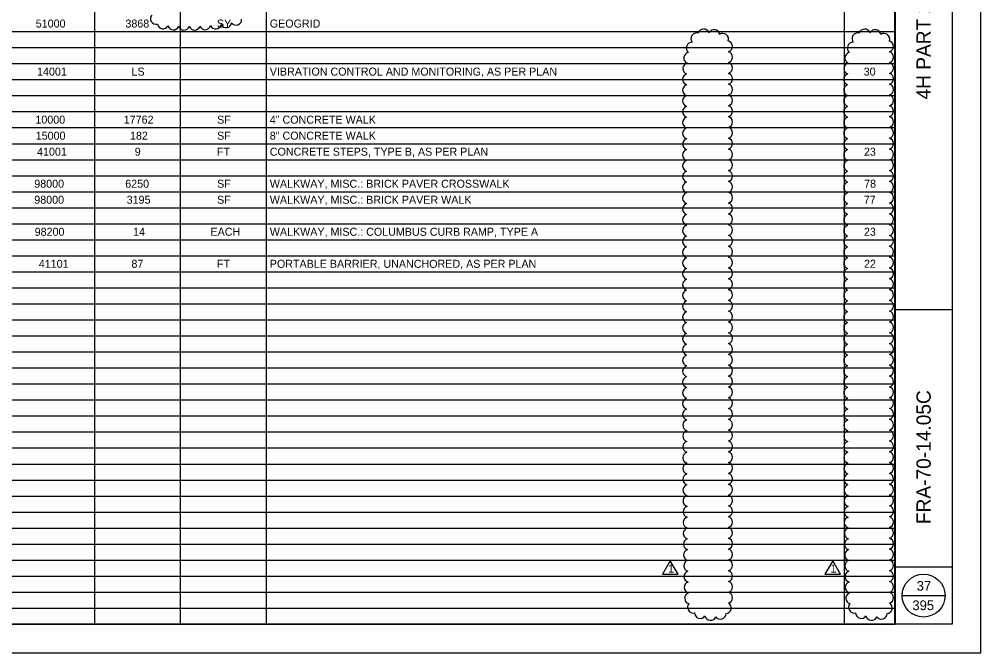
# Model space of a CAD drawing. Extents: x 0 to 34, y 0 to 22.
# Drawn here: x 17.19 to 34, y 0 to 11.08 of the extents above; entities that cross this region are included whole.
import ezdxf

# ---------------------------------------------------------------- set-up
doc = ezdxf.new("R2010")
doc.units = 0
for name, color, linetype in [('SH_Border', 7, 'Continuous'), ('SH_Cut_Line', 7, 'Continuous'), ('SH_Data', 7, 'Continuous'), ('SH_Text', 7, 'Continuous'), ('TX_P_1000', 7, 'Continuous')]:
    doc.layers.add(name, color=color, linetype=linetype)

msp = doc.modelspace()

# ---------------------------------------------------------------- linework, layer by layer
at = {"layer": 'SH_Border'}
for p, q in [((32.5, 0.5), (32.5, 21.5)), ((32.5, 6), (33.5, 6)), ((32.5, 1.5), (33.5, 1.5))]:
    msp.add_line(p, q, dxfattribs=at)
msp.add_lwpolyline([(2, 21.5), (33.5, 21.5), (33.5, 0.5), (2, 0.5)], close=True, dxfattribs=at)
at = {"layer": 'SH_Cut_Line'}
msp.add_lwpolyline([(0, 0), (34, 0), (34, 22), (0, 22)], close=True, dxfattribs=at)
at = {"layer": 'SH_Data'}
for p, q in [((18.504, 21.5), (18.504, 0.5)), ((20.002, 21.5), (20.002, 0.5)), ((21.501, 21.5), (21.501, 0.5)), ((31.614, 21.5), (31.614, 0.5)), ((32.504, 21.5), (32.504, 0.5)), ((2, 10.86), (32.504, 10.86)), ((2, 10.58), (32.504, 10.58)), ((2, 10.3), (32.504, 10.3)), ((2, 10.02), (32.504, 10.02)), ((2, 9.74), (32.504, 9.74)), ((2, 9.46), (32.504, 9.46)), ((2, 9.18), (32.504, 9.18)), ((2, 8.9), (32.504, 8.9)), ((2, 8.62), (32.504, 8.62)), ((2, 8.34), (32.504, 8.34)), ((2, 8.06), (32.504, 8.06)), ((2, 7.78), (32.504, 7.78)), ((2, 7.5), (32.504, 7.5)), ((2, 7.22), (32.504, 7.22)), ((2, 6.94), (32.504, 6.94)), ((2, 6.66), (32.504, 6.66)), ((2, 6.38), (32.504, 6.38)), ((2, 6.1), (32.504, 6.1)), ((2, 5.82), (32.504, 5.82)), ((2, 5.54), (32.504, 5.54)), ((2, 5.26), (32.504, 5.26)), ((2, 4.98), (32.504, 4.98)), ((2, 4.7), (32.504, 4.7)), ((2, 4.42), (32.504, 4.42)), ((2, 4.14), (32.504, 4.14)), ((2, 3.86), (32.504, 3.86)), ((2, 3.58), (32.504, 3.58)), ((2, 3.3), (32.504, 3.3)), ((2, 3.02), (32.504, 3.02)), ((2, 2.74), (32.504, 2.74)), ((2, 2.46), (32.504, 2.46)), ((2, 2.18), (32.504, 2.18)), ((2, 1.9), (32.504, 1.9)), ((2, 1.62), (32.504, 1.62)), ((2, 1.34), (32.504, 1.34)), ((2, 1.06), (32.504, 1.06)), ((32.625, 1), (33.375, 1)), ((2, 0.78), (32.504, 0.78)), ((2, 0.5), (32.504, 0.5))]:
    msp.add_line(p, q, dxfattribs=at)
msp.add_circle((33, 1), 0.375, dxfattribs=at)
at = {"layer": 'TX_P_1000'}
for points in [[(28.571, 1.608), (28.435, 1.372), (28.708, 1.372)], [(31.411, 1.608), (31.274, 1.372), (31.547, 1.372)]]:
    msp.add_lwpolyline(points, close=True, dxfattribs=at)
for centre, radius, start, end in [((19.578, 11.085), 0.0976, 139.2641, 284.2641), ((19.699, 11.005), 0.0976, 188.32, 333.32), ((19.88, 10.986), 0.0976, 195.1082, 340.1082), ((20.065, 10.982), 0.0976, 197.1836, 342.1836), ((20.251, 10.983), 0.0976, 198.6029, 343.6029), ((20.436, 10.99), 0.0976, 200.3873, 345.3873), ((20.62, 11.003), 0.0976, 202.8824, 347.8824), ((20.803, 11.026), 0.0976, 206.7346, 351.7346), ((20.977, 11.072), 0.0977, 217.3339, 2.3339), ((29.031, 10.736), 0.099, 74.4093, 219.4093), ((29.153, 10.805), 0.0991, 19.2496, 164.2496), ((29.336, 10.794), 0.0991, 9.041, 154.041), ((29.491, 10.729), 0.099, 340.6755, 125.6755), ((31.847, 10.736), 0.099, 74.4093, 219.4093), ((31.969, 10.805), 0.0991, 19.2496, 164.2496), ((32.152, 10.794), 0.0991, 9.041, 154.041), ((32.308, 10.729), 0.099, 340.6755, 125.6755), ((28.95, 10.574), 0.0991, 87.314, 232.314), ((29.557, 10.601), 0.0992, 288.6913, 73.6913), ((31.766, 10.574), 0.0991, 87.314, 232.314), ((32.373, 10.601), 0.0992, 288.6913, 73.6913), ((28.906, 10.398), 0.0991, 99.6335, 244.6335), ((29.559, 10.413), 0.0991, 287.5, 72.5), ((31.722, 10.398), 0.0991, 99.6335, 244.6335), ((32.375, 10.413), 0.0991, 287.5, 72.5), ((28.889, 10.213), 0.0991, 105.2456, 250.2456), ((29.559, 10.224), 0.0991, 287.5, 72.5), ((31.706, 10.213), 0.0991, 105.2456, 250.2456), ((32.375, 10.224), 0.0991, 287.5, 72.5), ((28.886, 10.025), 0.0991, 107.4797, 252.4797), ((29.559, 10.035), 0.0991, 287.5, 72.5), ((31.702, 10.025), 0.0991, 107.4797, 252.4797), ((32.375, 10.035), 0.0991, 287.5, 72.5), ((28.885, 9.836), 0.0991, 107.5, 252.5), ((29.559, 9.846), 0.0991, 287.5, 72.5), ((31.702, 9.836), 0.0991, 107.5, 252.5), ((32.375, 9.846), 0.0991, 287.5, 72.5), ((28.885, 9.647), 0.0991, 107.5, 252.5), ((29.559, 9.657), 0.0991, 287.5, 72.5), ((31.702, 9.647), 0.0991, 107.5, 252.5), ((32.375, 9.657), 0.0991, 287.5, 72.5), ((28.885, 9.458), 0.0991, 107.5, 252.5), ((29.559, 9.468), 0.0991, 287.5, 72.5), ((31.702, 9.458), 0.0991, 107.5, 252.5), ((32.375, 9.468), 0.0991, 287.5, 72.5), ((28.885, 9.269), 0.0991, 107.5, 252.5), ((29.559, 9.279), 0.0991, 287.5, 72.5), ((31.702, 9.269), 0.0991, 107.5, 252.5), ((32.375, 9.279), 0.0991, 287.5, 72.5), ((28.885, 9.08), 0.0991, 107.5, 252.5), ((29.559, 9.09), 0.0991, 287.5, 72.5), ((31.702, 9.08), 0.0991, 107.5, 252.5), ((32.375, 9.09), 0.0991, 287.5, 72.5), ((28.885, 8.891), 0.0991, 107.5, 252.5), ((29.559, 8.901), 0.0991, 287.5, 72.5), ((31.702, 8.891), 0.0991, 107.5, 252.5), ((32.375, 8.901), 0.0991, 287.5, 72.5), ((28.885, 8.702), 0.0991, 107.5, 252.5), ((29.559, 8.712), 0.0991, 287.5, 72.5), ((31.702, 8.702), 0.0991, 107.5, 252.5), ((32.375, 8.712), 0.0991, 287.5, 72.5), ((28.885, 8.513), 0.0991, 107.5, 252.5), ((29.559, 8.523), 0.0991, 287.5, 72.5), ((31.702, 8.513), 0.0991, 107.5, 252.5), ((32.375, 8.523), 0.0991, 287.5, 72.5), ((28.885, 8.324), 0.0991, 107.5, 252.5), ((29.559, 8.334), 0.0991, 287.5, 72.5), ((31.702, 8.324), 0.0991, 107.5, 252.5), ((32.375, 8.334), 0.0991, 287.5, 72.5), ((28.885, 8.135), 0.0991, 107.5, 252.5), ((29.559, 8.145), 0.0991, 287.5, 72.5), ((31.702, 8.135), 0.0991, 107.5, 252.5), ((32.375, 8.145), 0.0991, 287.5, 72.5), ((28.885, 7.946), 0.0991, 107.5, 252.5), ((29.559, 7.956), 0.0991, 287.5, 72.5), ((31.702, 7.946), 0.0991, 107.5, 252.5), ((32.375, 7.956), 0.0991, 287.5, 72.5), ((28.885, 7.757), 0.0991, 107.5, 252.5), ((29.559, 7.767), 0.0991, 287.5, 72.5), ((31.702, 7.757), 0.0991, 107.5, 252.5), ((32.375, 7.767), 0.0991, 287.5, 72.5), ((28.885, 7.568), 0.0991, 107.5, 252.5), ((29.559, 7.578), 0.0991, 287.5, 72.5), ((31.702, 7.568), 0.0991, 107.5, 252.5), ((32.375, 7.578), 0.0991, 287.5, 72.5), ((28.885, 7.379), 0.0991, 107.5, 252.5), ((29.559, 7.389), 0.0991, 287.5, 72.5), ((31.702, 7.379), 0.0991, 107.5, 252.5), ((32.375, 7.389), 0.0991, 287.5, 72.5), ((28.885, 7.19), 0.0991, 107.5, 252.5), ((29.559, 7.2), 0.0991, 287.5, 72.5), ((31.702, 7.19), 0.0991, 107.5, 252.5), ((32.375, 7.2), 0.0991, 287.5, 72.5), ((28.885, 7.001), 0.0991, 107.5, 252.5), ((29.559, 7.011), 0.0991, 287.5, 72.5), ((31.702, 7.001), 0.0991, 107.5, 252.5), ((32.375, 7.011), 0.0991, 287.5, 72.5), ((28.885, 6.812), 0.0991, 107.5, 252.5), ((29.559, 6.822), 0.0991, 287.5, 72.5), ((31.702, 6.812), 0.0991, 107.5, 252.5), ((32.375, 6.822), 0.0991, 287.5, 72.5), ((29.559, 6.633), 0.0991, 287.5, 72.5), ((32.375, 6.633), 0.0991, 287.5, 72.5), ((28.885, 6.623), 0.0991, 107.5, 252.5), ((31.702, 6.623), 0.0991, 107.5, 252.5), ((28.885, 6.434), 0.0991, 107.5, 252.5), ((29.559, 6.444), 0.0991, 287.5, 72.5), ((31.702, 6.434), 0.0991, 107.5, 252.5), ((32.375, 6.444), 0.0991, 287.5, 72.5), ((28.885, 6.245), 0.0991, 107.5, 252.5), ((29.559, 6.255), 0.0991, 287.5, 72.5), ((31.702, 6.245), 0.0991, 107.5, 252.5), ((32.375, 6.255), 0.0991, 287.5, 72.5), ((28.885, 6.056), 0.0991, 107.5, 252.5), ((29.559, 6.066), 0.0991, 287.5, 72.5), ((31.702, 6.056), 0.0991, 107.5, 252.5), ((32.375, 6.066), 0.0991, 287.5, 72.5), ((28.885, 5.867), 0.0991, 107.5, 252.5), ((29.559, 5.877), 0.0991, 287.5, 72.5), ((31.702, 5.867), 0.0991, 107.5, 252.5), ((32.375, 5.877), 0.0991, 287.5, 72.5), ((28.885, 5.678), 0.0991, 107.5, 252.5), ((29.559, 5.688), 0.0991, 287.5, 72.5), ((31.702, 5.678), 0.0991, 107.5, 252.5), ((32.375, 5.688), 0.0991, 287.5, 72.5), ((28.885, 5.489), 0.0991, 107.5, 252.5), ((29.559, 5.499), 0.0991, 287.5, 72.5), ((31.702, 5.489), 0.0991, 107.5, 252.5), ((32.375, 5.499), 0.0991, 287.5, 72.5), ((28.885, 5.3), 0.0991, 107.5, 252.5), ((29.559, 5.31), 0.0991, 287.5, 72.5), ((31.702, 5.3), 0.0991, 107.5, 252.5), ((32.375, 5.31), 0.0991, 287.5, 72.5), ((29.559, 5.121), 0.0991, 287.5, 72.5), ((32.375, 5.121), 0.0991, 287.5, 72.5), ((28.886, 5.111), 0.0991, 107.5091, 252.5091), ((31.702, 5.111), 0.0991, 107.5091, 252.5091), ((28.886, 4.922), 0.0991, 107.5258, 252.5258), ((29.559, 4.932), 0.0991, 287.5, 72.5), ((31.702, 4.922), 0.0991, 107.5258, 252.5258), ((32.375, 4.932), 0.0991, 287.5, 72.5), ((28.886, 4.733), 0.0991, 107.5437, 252.5437), ((29.559, 4.743), 0.0991, 287.5, 72.5), ((31.702, 4.733), 0.0991, 107.5437, 252.5437), ((32.375, 4.743), 0.0991, 287.5, 72.5), ((28.886, 4.544), 0.0991, 107.5629, 252.5629), ((29.559, 4.554), 0.0991, 287.5, 72.5), ((31.702, 4.544), 0.0991, 107.5629, 252.5629), ((32.375, 4.554), 0.0991, 287.5, 72.5), ((28.886, 4.355), 0.0991, 107.5836, 252.5836), ((29.559, 4.365), 0.0991, 287.5, 72.5), ((31.703, 4.355), 0.0991, 107.5836, 252.5836), ((32.375, 4.365), 0.0991, 287.5, 72.5), ((28.886, 4.166), 0.0991, 107.606, 252.606), ((29.559, 4.176), 0.0991, 287.5, 72.5), ((31.703, 4.166), 0.0991, 107.606, 252.606), ((32.375, 4.176), 0.0991, 287.5, 72.5), ((28.887, 3.977), 0.0991, 107.6303, 252.6303), ((29.559, 3.987), 0.0991, 287.5, 72.5), ((31.703, 3.977), 0.0991, 107.6303, 252.6303), ((32.375, 3.987), 0.0991, 287.5, 72.5), ((28.887, 3.788), 0.0991, 107.6568, 252.6568), ((29.559, 3.797), 0.0991, 287.5, 72.5), ((31.704, 3.788), 0.0991, 107.6568, 252.6568), ((32.375, 3.797), 0.0991, 287.5, 72.5), ((29.559, 3.608), 0.0991, 287.5, 72.5), ((32.375, 3.608), 0.0991, 287.5, 72.5), ((28.888, 3.599), 0.0991, 107.6859, 252.6859), ((31.704, 3.599), 0.0991, 107.6859, 252.6859), ((28.889, 3.41), 0.0991, 107.718, 252.718), ((29.559, 3.419), 0.0991, 287.5, 72.5), ((31.705, 3.41), 0.0991, 107.718, 252.718), ((32.375, 3.419), 0.0991, 287.5, 72.5), ((28.889, 3.221), 0.0991, 107.7537, 252.7537), ((29.559, 3.23), 0.0991, 287.5, 72.5), ((31.706, 3.221), 0.0991, 107.7537, 252.7537), ((32.375, 3.23), 0.0991, 287.5, 72.5), ((28.89, 3.032), 0.0991, 107.7938, 252.7938), ((29.559, 3.041), 0.0991, 287.5, 72.5), ((31.707, 3.032), 0.0991, 107.7938, 252.7938), ((32.375, 3.041), 0.0991, 287.5, 72.5), ((28.891, 2.843), 0.0991, 107.8391, 252.8391), ((29.559, 2.852), 0.0991, 287.5, 72.5), ((31.708, 2.843), 0.0991, 107.8391, 252.8391), ((32.375, 2.852), 0.0991, 287.5, 72.5), ((28.892, 2.654), 0.0991, 107.8909, 252.8909), ((29.559, 2.663), 0.0991, 287.5, 72.5), ((31.709, 2.654), 0.0991, 107.8909, 252.8909), ((32.375, 2.663), 0.0991, 287.5, 72.5), ((28.894, 2.465), 0.0991, 107.951, 252.951), ((29.559, 2.474), 0.0991, 287.5, 72.5), ((31.71, 2.465), 0.0991, 107.951, 252.951), ((32.375, 2.474), 0.0991, 287.5, 72.5), ((28.895, 2.276), 0.0991, 108.0219, 253.0219), ((29.559, 2.285), 0.0991, 287.5, 72.5), ((31.712, 2.276), 0.0991, 108.0219, 253.0219), ((32.375, 2.285), 0.0991, 287.5, 72.5), ((29.559, 2.096), 0.0991, 287.5, 72.5), ((32.375, 2.096), 0.0991, 287.5, 72.5), ((28.897, 2.087), 0.0991, 108.1071, 253.1071), ((31.714, 2.087), 0.0991, 108.1071, 253.1071), ((28.899, 1.898), 0.0991, 108.2123, 253.2123), ((29.559, 1.907), 0.0991, 287.5, 72.5), ((31.716, 1.898), 0.0991, 108.2123, 253.2123), ((32.375, 1.907), 0.0991, 287.5, 72.5), ((28.902, 1.709), 0.0991, 108.3469, 253.3469), ((29.559, 1.718), 0.0991, 287.5, 72.5), ((31.719, 1.709), 0.0991, 108.3469, 253.3469), ((32.375, 1.718), 0.0991, 287.5, 72.5), ((28.905, 1.521), 0.0991, 108.5276, 253.5276), ((29.559, 1.529), 0.0991, 287.5, 72.5), ((31.722, 1.521), 0.0991, 108.5276, 253.5276), ((32.375, 1.529), 0.0991, 287.5, 72.5), ((28.909, 1.332), 0.0991, 108.7891, 253.7891), ((29.559, 1.34), 0.0991, 287.5, 72.5), ((31.725, 1.332), 0.0991, 108.7891, 253.7891), ((32.375, 1.34), 0.0991, 287.5, 72.5), ((28.914, 1.143), 0.0991, 109.2189, 254.2189), ((29.559, 1.151), 0.0991, 287.5, 72.5), ((31.73, 1.143), 0.0991, 109.2189, 254.2189), ((32.375, 1.151), 0.0991, 287.5, 72.5), ((28.921, 0.955), 0.0991, 110.1571, 255.1571), ((29.559, 0.962), 0.0991, 287.5, 72.5), ((31.738, 0.955), 0.0991, 110.1571, 255.1571), ((32.375, 0.962), 0.0991, 287.5, 72.5), ((28.971, 0.794), 0.0991, 139.2663, 284.2663), ((29.538, 0.783), 0.0991, 274.2898, 59.2898), ((31.787, 0.794), 0.0991, 139.2663, 284.2663), ((32.354, 0.783), 0.0991, 274.2898, 59.2898), ((29.094, 0.7), 0.0991, 180.783, 325.783), ((29.446, 0.685), 0.0991, 214.5703, 359.5703), ((31.911, 0.7), 0.0991, 180.783, 325.783), ((32.263, 0.685), 0.0991, 214.5703, 359.5703), ((29.273, 0.666), 0.0991, 192.8167, 337.8167), ((32.089, 0.666), 0.0991, 192.8167, 337.8167)]:
    msp.add_arc(centre, radius, start, end, dxfattribs=at)

# ---------------------------------------------------------------- texts
at = {"layer": 'SH_Data'}
for s, p in [('4H PART 2 GENERAL SUMMARY', (33.125, 9.672)), ('FRA-70-14.05C', (33.125, 2.249))]:
    msp.add_text(s, height=0.25, rotation=90, dxfattribs=at).set_placement(p)
at = {"layer": 'SH_Text'}
for s, height, p in [('51000', 0.14, (17.474, 10.93)), ('3868', 0.14, (19.042, 10.93)), ('SY', 0.14, (20.642, 10.93)), ('GEOGRID', 0.14, (21.567, 10.93)), ('14001', 0.14, (17.497, 10.09)), ('LS', 0.14, (19.149, 10.09)), ('VIBRATION CONTROL AND MONITORING, AS PER PLAN', 0.14, (21.567, 10.09)), ('30', 0.14, (31.953, 10.09)), ('10000', 0.14, (17.468, 9.25)), ('17762', 0.14, (19.013, 9.25)), ('SF', 0.14, (20.645, 9.25)), ('4" CONCRETE WALK', 0.14, (21.567, 9.25)), ('15000', 0.14, (17.474, 8.97)), ('182', 0.14, (19.122, 8.97)), ('SF', 0.14, (20.645, 8.97)), ('8" CONCRETE WALK', 0.14, (21.567, 8.97)), ('41001', 0.14, (17.497, 8.69)), ('9', 0.14, (19.205, 8.69)), ('FT', 0.14, (20.642, 8.69)), ('CONCRETE STEPS, TYPE B, AS PER PLAN', 0.14, (21.567, 8.69)), ('23', 0.14, (31.957, 8.69)), ('98000', 0.14, (17.448, 8.13)), ('6250', 0.14, (19.039, 8.13)), ('SF', 0.14, (20.645, 8.13)), ('WALKWAY, MISC.: BRICK PAVER CROSSWALK', 0.14, (21.567, 8.13)), ('78', 0.14, (31.96, 8.13)), ('98000', 0.14, (17.448, 7.85)), ('3195', 0.14, (19.064, 7.85)), ('SF', 0.14, (20.645, 7.85)), ('WALKWAY, MISC.: BRICK PAVER WALK', 0.14, (21.567, 7.85)), ('77', 0.14, (31.954, 7.85)), ('98200', 0.14, (17.455, 7.29)), ('14', 0.14, (19.177, 7.29)), ('EACH', 0.14, (20.53, 7.29)), ('WALKWAY, MISC.: COLUMBUS CURB RAMP, TYPE A', 0.14, (21.567, 7.29)), ('23', 0.14, (31.957, 7.29)), ('41101', 0.14, (17.528, 6.73)), ('87', 0.14, (19.147, 6.73)), ('FT', 0.14, (20.642, 6.73)), ('PORTABLE BARRIER, UNANCHORED, AS PER PLAN', 0.14, (21.567, 6.73)), ('22', 0.14, (31.958, 6.73)), ('37', 0.17, (32.879, 1.085)), ('395', 0.17, (32.804, 0.745))]:
    msp.add_text(s, height=height, dxfattribs=at).set_placement(p)
at = {"layer": 'TX_P_1000'}
for p in [(28.532, 1.403), (31.372, 1.403)]:
    msp.add_text('1', height=0.14, rotation=360, dxfattribs=at).set_placement(p)

doc.saveas('drawing.dxf')
